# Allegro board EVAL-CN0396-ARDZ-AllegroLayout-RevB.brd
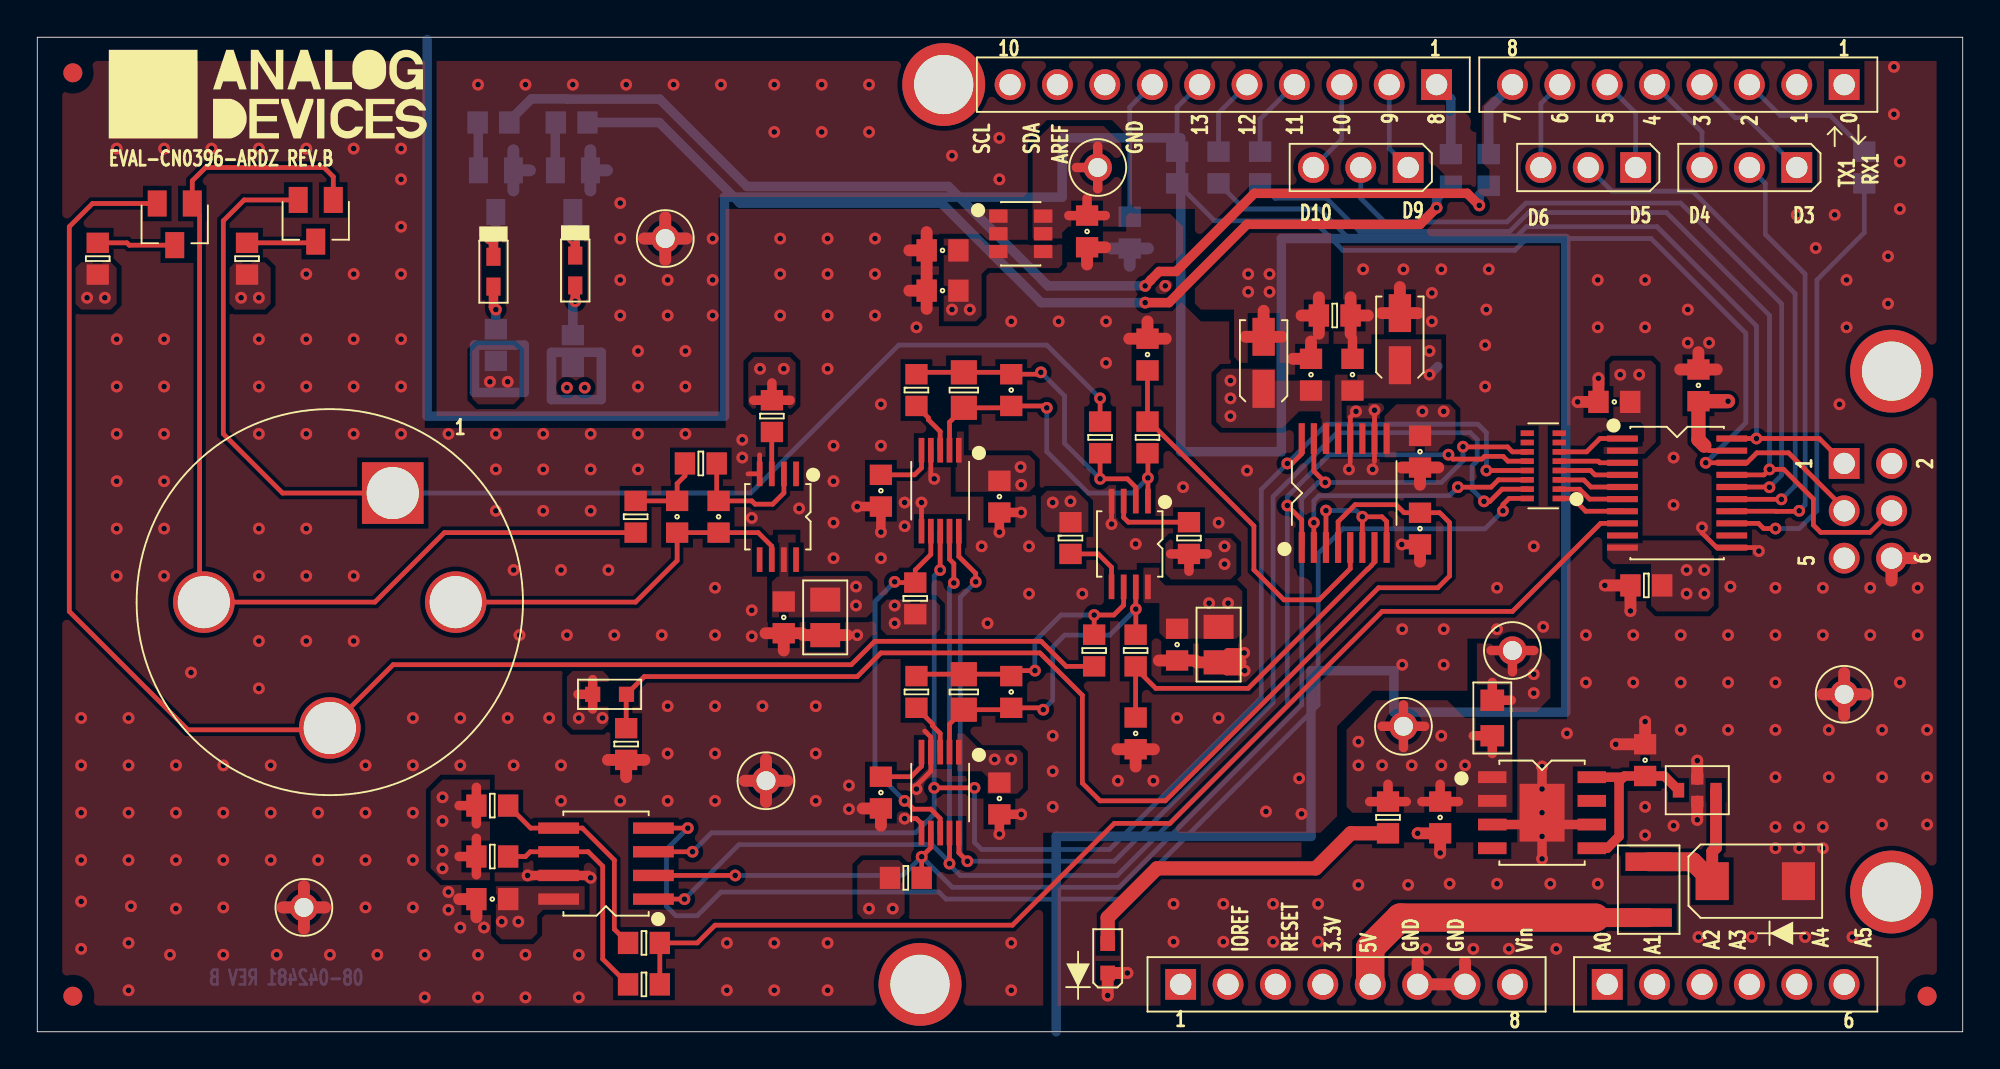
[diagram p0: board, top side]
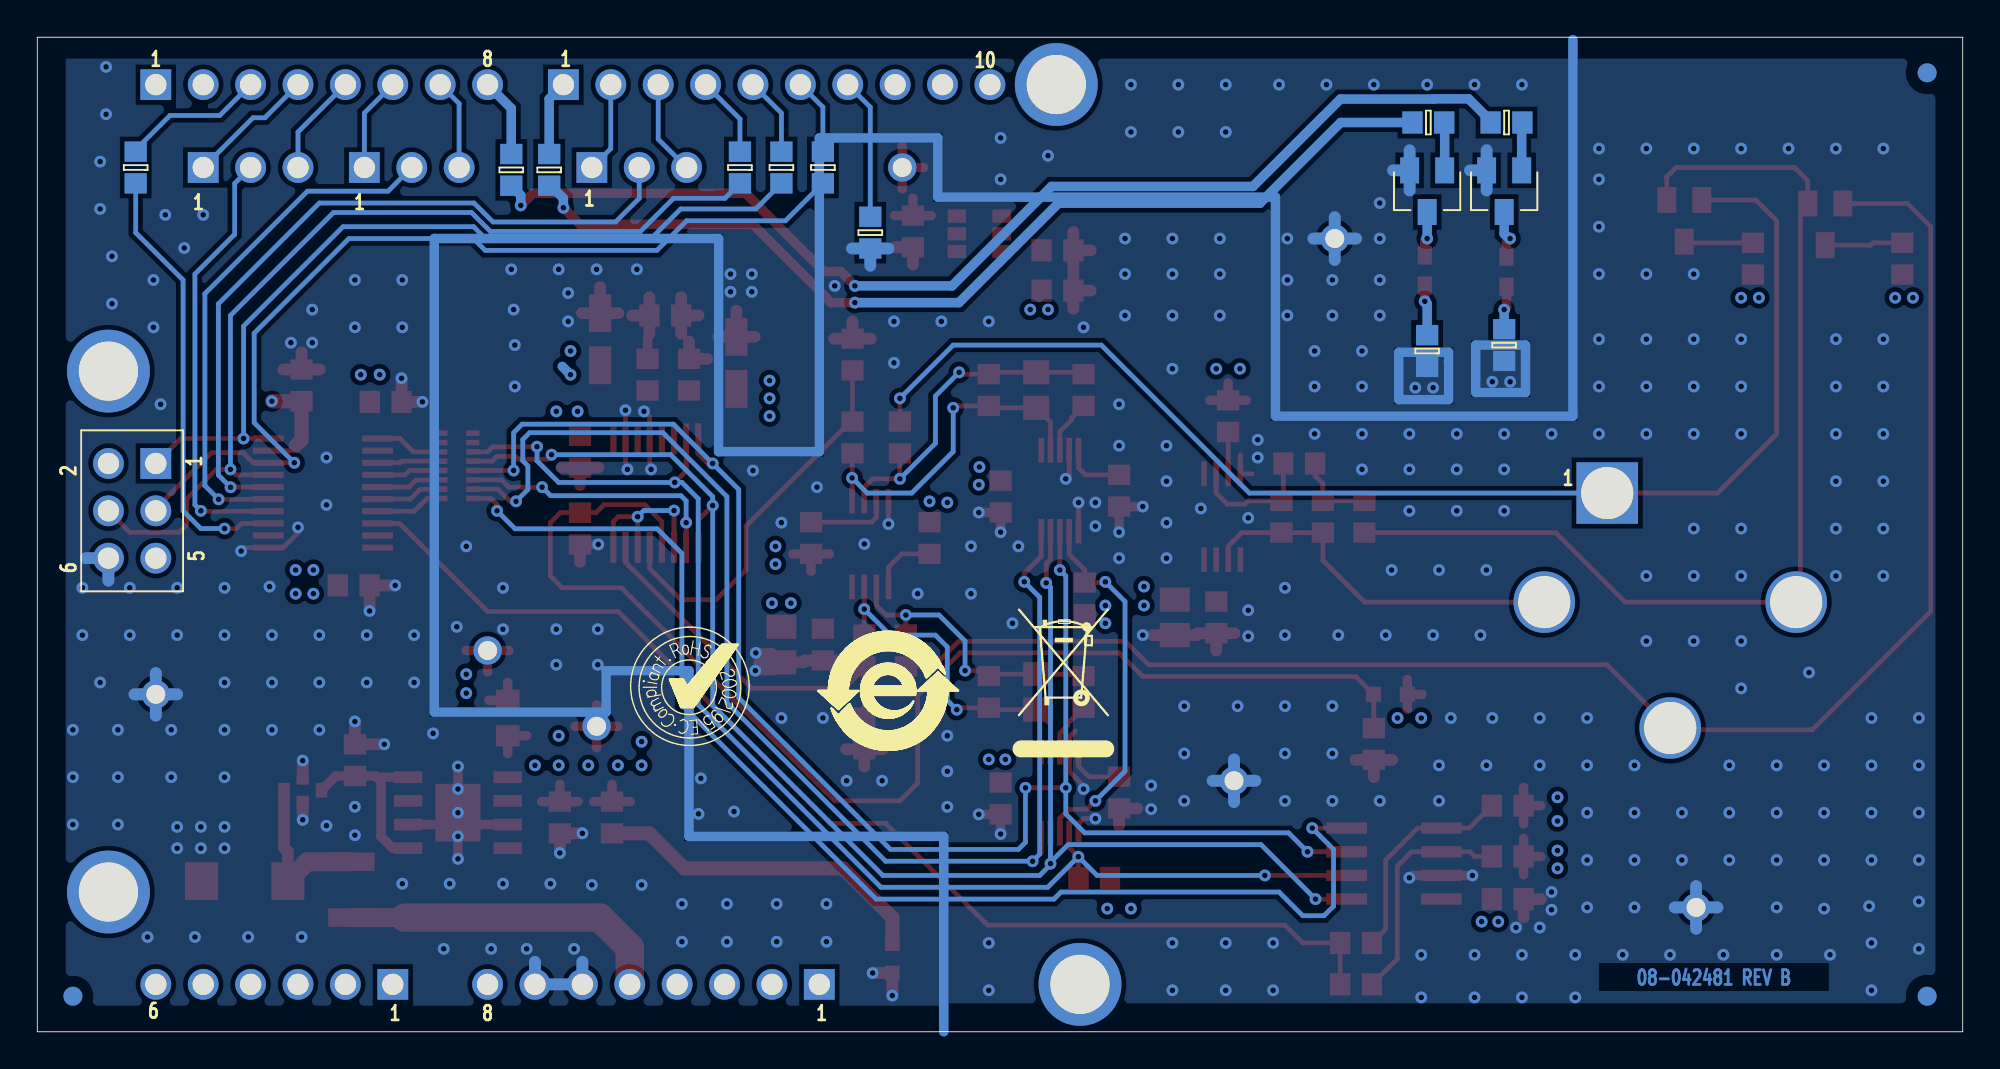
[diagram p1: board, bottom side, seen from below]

Outline 103.19 x 53.34 mm; copper layers: TOP, L2_GND, L3_PWR, BOTTOM. Coordinates in mm from the lower left corner of the outline.
Outline path: 0,53.34 0,0 103.19,0 103.19,53.34 0,53.34

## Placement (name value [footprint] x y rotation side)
A1  ADA4528-2ARMZ  [MSOP8]  58.55 26.16 180 top
A2  ADA4528-1ARMZ  [MSOP8]  39.69 27.62 180 top
AD5270_CS  SAMTECTSW10608GS3PIN  [CNBERG1X3H205LD36]  85.66 46.36 180 top
AD7798_CS  SAMTECTSW10608GS3PIN  [CNBERG1X3H205LD36]  73.47 46.36 180 top
ADT7310_CS  SAMTECTSW10608GS3PIN  [CNBERG1X3H205LD36]  94.3 46.36 180 top
ANALOG  SSQ-106-03-G-S  [CNSAMTECSSQ-106-XX-X-S]  84.14 2.54 0 top
C1  1uF  [C0603]  48.51 39.75 180 top
C2  0.1uF  [C0603]  48.51 41.91 180 top
C3  0.022uF  [C0603]  36.51 27.62 270 top
C4  0.022uF  [C0603]  34.29 27.62 90 top
C5  0.1uF  [C0603]  56.26 42.93 270 top
C6  4.7uF  [C0805H53]  42.23 22.23 270 top
C7  0.1uF  [C0603]  40 22.23 270 top
C8  0.022uF  [C0603]  52.2 34.42 270 top
C9  10uF  [C0603]  59.5 36.32 90 top
C10  0.1uF  [C0603]  51.56 28.7 270 top
C11  1uF  [C0603]  45.21 29.02 270 top
C12  1.0UF  [C0805-4P]  88.96 12.95 180 top
C13  1uF  [C0603]  86.17 14.57 90 top
C14  1uF  [C0603]  75.18 11.49 270 top
C15  0.1uF  [C0603]  51.56 12.51 270 top
C16  1uF  [C0603]  45.21 12.83 270 top
C17  4.7uF  [C0805H53]  63.31 20.76 270 top
C18  0.1uF  [C0603]  74.1 31.12 270 top
C19  0.1uF  [C0603]  61.09 20.76 270 top
C20  0.1uF  [C0603]  70.48 35.24 270 top
C21  0.1uF  [C0603]  89.03 34.67 270 top
C22  0.1uF  [C0603]  84.52 33.78 180 top
C23  0.022uF  [C0603]  52.2 18.22 270 top
C24  10uF  [C0603]  58.86 16 270 top
C25  0.1uF  [C0603]  24.38 7.11 180 top
C26  0.1uF  [C0603]  74.1 26.99 270 top
C27  10uF  [C3216]  73.03 37.15 90 top
C28  10uF  [C3216]  65.72 35.88 90 top
C29  0.1uF  [C0603]  68.26 35.24 90 top
CR1  1SMB5927BT3G  [DO214AA]  92.08 8.08 0 top
DGND1  5001  [CNKEY5001TP]  33.66 42.55 0 top
DGND2  5001  [CNKEY5001TP]  96.84 18.1 0 top
DIGI0  SSQ-108-03-G-S  [CNSAMTECSSQ-108-XX-X-S]  96.84 50.8 180 top
DIGI1  SSQ-110-03-G-S  [CNSAMTECSSQ-110-XX-X-S]  74.99 50.8 180 top
E1  330OHM  [L0805]  77.98 16.83 90 top
F1  0.35A  [F1210]  86.36 7.62 90 top
GND1  5001  [CNKEY5001TP]  14.29 6.67 0 top
GND2  5001  [CNKEY5001TP]  39.05 13.46 0 top
ICSP  SSQ-103-03-G-D  [CNSAMTECSSQ-103-XX-X-D]  96.84 30.48 270 bottom
LED1  LTST-C190CKT  [LED0603]  28.83 40.83 270 top
LED2  LTST-C190CKT  [LED0603]  24.45 40.77 270 top
M1  COH-A2  [MCOH-A2_SKTLD98]  19.05 28.89 180 top
NOREF  -  []  0 0 0 top
NOREF#2  -  []  0 53.34 270 top
NOREF#3  -  [unnamed#2]  101.28 1.91 0 top
NOREF#4  -  []  180.15 63.37 0 top
NOREF#5  -  []  0 0 0 top
NOREF#6  -  []  101.28 1.91 0 top
NOREF#7  -  []  -111.82 -234.12 0 top
NOREF#8  -  [unnamed#2]  47.31 2.54 0 top
NOREF#9  -  [unnamed#2]  1.91 51.44 0 top
NOREF#10  -  []  103.19 53.34 0 top
NOREF#11  -  []  -111.82 -234.12 0 top
NOREF#12  -  [unnamed#2]  99.38 35.43 0 top
NOREF#13  -  []  -36.77 -49.28 0 top
NOREF#14  -  []  0 53.34 0 top
NOREF#15  -  [unnamed#2]  48.58 50.81 0 top
NOREF#16  -  []  12.38 50.29 0 top
NOREF#17  -  []  103.19 0 0 top
NOREF#18  -  []  59.12 76.07 0 top
NOREF#19  -  []  0 0 90 top
NOREF#20  -  []  101.28 1.91 0 top
NOREF#21  -  []  -11.94 12.65 0 top
NOREF#22  -  []  103.19 0 0 top
NOREF#23  -  [unnamed#2]  1.91 1.91 0 top
NOREF#24  -  []  103.19 53.34 180 top
NOREF#25  -  []  103.19 0 90 top
NOREF#26  -  [unnamed#2]  99.38 7.49 0 top
NOREF#27  -  []  -63.94 154.56 0 top
NOREF#28  -  []  -111.82 -234.12 0 top
NOREF#29  -  []  20.59 22.13 0 top
NOREF#30  -  [unnamed#2]  101.28 1.91 180 bottom
NOREF#31  -  [unnamed#2]  1.91 51.44 180 bottom
NOREF#32  -  []  68.26 18.42 180 bottom
NOREF#33  -  []  57.59 18.29 180 bottom
NOREF#34  -  []  48.2 19.81 180 bottom
NOREF#35  -  [unnamed#2]  1.91 1.91 180 bottom
P1  SSQ-108-03-G-S  [CNSAMTECSSQ-108-XX-X-S]  61.28 2.54 0 top
POWER  SML-LX0603GW-TR  [LED0603-2]  57.37 3.94 90 top
Q1  MMBFJ270  [SOT23]  14.92 43.5 180 top
Q2  MMBFJ270  [SOT23]  7.37 43.31 180 top
Q3  MMBT2222A  [SOT23]  28.7 45.09 0 bottom
Q4  MMBT2222A  [SOT23]  24.57 45.09 0 bottom
R1  12.4K  [R0603]  39.37 33.02 270 top
R2  12.4K  [R0603]  35.56 30.48 180 top
R3  12.4K  [R0603]  32.07 27.62 270 top
R4  1MEG  [R0603]  11.24 41.47 90 top
R5  33  [R0603]  56.96 31.88 270 top
R6  165  [R0603]  72.39 11.49 270 top
R7  12.4K  [R0603]  61.72 26.48 90 top
R8  TBD0805  [R0805]  49.66 34.42 270 top
R9  100K  [R0603]  59.5 31.88 90 top
R10  33  [R0603]  56.64 20.45 90 top
R11  12.4K  [R0603]  55.37 26.48 270 top
R12  TBD0805  [R0805]  49.66 18.22 270 top
R13  100K  [R0603]  58.86 20.45 270 top
R14  0  [R0603]  65.53 46.36 90 bottom
R15  0  [R0603]  63.31 46.36 90 bottom
R16  0  [R0603]  61.09 46.36 90 bottom
R17  0  [R0603]  58.55 42.86 90 bottom
R18  100K  [R0603]  86.23 23.94 180 top
R19  2.2K  [R0603]  47.05 23.24 270 top
R20  100K  [R0603]  24.38 12.13 0 top
R21  100K  [R0603]  24.38 9.4 0 top
R22  2.2K  [R0603]  46.55 8.25 180 top
R23  1MEG  [R0603]  3.24 41.47 90 top
R24  0  [R0603]  47.12 34.42 270 top
R25  0  [R0603]  47.12 18.22 270 top
R26  18.7K  [R0603]  31.56 15.43 270 top
R27  1K  [R0603]  28.64 48.77 180 bottom
R28  249  [R0603]  28.7 36.51 90 bottom
R29  1K  [R0603]  24.45 48.77 180 bottom
R30  249  [R0603]  24.57 36.83 90 bottom
R31  0  [R0603]  69.53 38.42 180 top
R32  0  [R0603]  97.92 46.36 90 bottom
R33  0  [R0603]  32.51 4.76 180 top
R34  0  [R0603]  32.51 2.54 180 top
R35  0  [R0603]  75.76 46.23 90 bottom
R36  0  [R0603]  77.79 46.23 90 bottom
REF  5002  [CNKEY5001TP]  56.83 46.36 90 top
RN1  47  [RESNET16]  80.71 30.35 90 top
RT1  10K  [R0603H35]  30.67 18.1 180 top
U1  AD7798BRUZ  [TSSOP16]  70.04 28.89 0 top
U2  AD5270BRMZ-20  [RM10]  48.39 29.02 180 top
U3  AD5270BRMZ-20  [RM10]  48.39 12.83 180 top
U4  ADT7310TRZ  [SO8]  30.48 9.02 90 top
U5  ADR3412ARJZ  [SOT23_6-2]  52.7 42.8 270 top
U6  ADP7102ARDZ-3.3  [SO8NB-PAD3_1X2_41]  80.64 11.75 270 top
U7  TXB0108PWR  [TSSOP20]  87.88 28.89 270 top
UNK3V3A  5002  [CNKEY5001TP]  73.22 16.38 0 top
UNK3V3D  5002  [CNKEY5001TP]  79.06 20.45 0 top

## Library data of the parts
A1 = ADA4528_2: Tolerance: N/A; User Part Number: UPN; part number: ADA4528_2_SM-ADA4528-2ARMZ,E018592,MSOP8; tolerance: N/A
A2 = ADOPAMP1V4: Tolerance: N/A; User Part Number: UPN; part number: ADOPAMP1V4_SM-ADA4528-1ARMZ,E014981,MSOP8; tolerance: N/A
AD5270_CS AD7798_CS ADT7310_CS = CN3P: User Part Number: UPN; Tolerance: N/A; part number: CN3P_TH-SAMTECTSW10608GS3PIN,E000812,CNBERG1X3H205LD36; tolerance: N/A
ANALOG = CN6P: User Part Number: UPN; Tolerance: N/A; part number: CN6P_TH-SSQ-106-03-G-S,E020477,CNSAMTECSSQ-106-XX-X-S; tolerance: N/A
C1 C11 C13 C14 C16 = CAP: Tolerance: 10; User Part Number: UPN; part number: CAP_SM-1UF,16V,10,E006882,C0603; tolerance: 10
C2 C5 C7 C10 C15 C18-C22 C25 C26 C29 = CAP: Tolerance: 10; User Part Number: UPN; part number: CAP_SM-0.1UF,25V,10,E022366,C0603; tolerance: 10
C3 C4 C8 C23 = CAP: Tolerance: 10; User Part Number: UPN; part number: CAP_SM-0.022UF,50V,10,E015725,C0603; tolerance: 10
C6 C17 = CAP: Tolerance: 10; User Part Number: UPN; part number: CAP_SM-4.7UF,25V,10,E006908,C0805H53; tolerance: 10
C9 C24 = CAP: Tolerance: 20; User Part Number: UPN; part number: CAP_SM-10UF,10V,20,E022682,C0603; tolerance: 20
C12 = CAP4P_V3: Tolerance: 20; User Part Number: UPN; part number: CAP4P_V3_SM-1.0UF,16V,20,E014204,C0805-4P; tolerance: 20
C27 C28 = CAPP: Tolerance: 10; User Part Number: UPN; part number: CAPP_SM-10UF,10V,10,E000690,C3216; tolerance: 10
CR1 = DIOZNR: User Part Number: UPN; Tolerance: N/A; part number: DIOZNR_SM-1SMB5927BT3G,12V,N/A,E006923,DO214AA; tolerance: N/A
DGND1 DGND2 GND1 GND2 = CNTP1P: Tolerance: N/A; User Part Number: UPN; part number: CNTP1P_TH-5001,E005347,CNKEY5001TP; tolerance: N/A
DIGI0 P1 = CN8P_A: User Part Number: UPN; Tolerance: N/A; part number: CN8P_A_TH-SSQ-108-03-G-S,E020478,CNSAMTECSSQ-108-XX-X-S; tolerance: N/A
DIGI1 = CN10P: User Part Number: UPN; Tolerance: N/A; part number: CN10P_TH-SSQ-110-03-G-S,E020479,CNSAMTECSSQ-110-XX-X-S; tolerance: N/A
E1 = FERRITE: Tolerance: 25; User Part Number: UPN; part number: FERRITE_SM-330OHM,25,E018120,L0805; tolerance: 25
F1 = FSFUSE: Tolerance: N/A; User Part Number: UPN; part number: FSFUSE_SM-0.35A,6V,E016918,F1210; tolerance: N/A
ICSP = CN6P: User Part Number: UPN; Tolerance: N/A; part number: CN6P_TH-SSQ-103-03-G-D,E020488,CNSAMTECSSQ-103-XX-X-D; tolerance: N/A
LED1 LED2 = DIOLED: Tolerance: N/A; User Part Number: UPN; part number: DIOLED_SM-LTST-C190CKT,1.8V,N/A,E023763,LED0603; tolerance: N/A
M1 = MOD_COH_A2: User Part Number: UPN; Tolerance: N/A; part number: MOD_COH_A2_TH-COH-A2,E024920,MCOH-A2_SKTLD98; tolerance: N/A
POWER = DIOLED: Tolerance: N/A; User Part Number: UPN; part number: DIOLED_SM-SML-LX0603GW-TR,2.2V,N/A,E018702,LED0603-2; tolerance: N/A
Q1 Q2 = TRANPJFET: User Part Number: UPN; Tolerance: N/A; part number: TRANPJFET_SM-MMBFJ270,E020756,SOT23; tolerance: N/A
Q3 Q4 = TRANMMBT4401: User Part Number: UPN; Tolerance: N/A; part number: TRANMMBT4401_SM-MMBT2222A,E006594,SOT23; tolerance: N/A
R1-R3 R7 R11 = RES: Tolerance: 1; User Part Number: UPN; part number: RES_SM-12.4K,E015341,1/10W,1,R0603; tolerance: 1
R4 R23 = RES: Tolerance: 1; User Part Number: UPN; part number: RES_SM-1MEG,E003682,1/10W,1,R0603; tolerance: 1
R5 R10 = RES: Tolerance: 5; User Part Number: UPN; part number: RES_SM-33,E026149,1/10W,5,R0603; tolerance: 5
R6 = RES: Tolerance: 1; User Part Number: UPN; part number: RES_SM-165,E003725,1/10W,1,R0603; tolerance: 1
R8 R12 = RES: User Part Number: UPN; part number: RES_SM-TBD0805,E004051,TBD0805,TBD0805,R0805
R9 R13 R18 R20 R21 = RES: Tolerance: 1; User Part Number: UPN; part number: RES_SM-100K,E010279,1/10W,1,R0603; tolerance: 1
R14-R17 R24 R25 R31-R36 = RES: Tolerance: 5; User Part Number: UPN; part number: RES_SM-0,E006826,1/10W,5,R0603; tolerance: 5
R19 R22 = RES: Tolerance: 1; User Part Number: UPN; part number: RES_SM-2.2K,E014667,1/10W,1,R0603; tolerance: 1
R26 = RES: Tolerance: 1; User Part Number: UPN; part number: RES_SM-18.7K,E011248,1/10W,1,R0603; tolerance: 1
R27 R29 = RES: Tolerance: 1; User Part Number: UPN; part number: RES_SM-1K,E003678,1/10W,1,R0603; tolerance: 1
R28 R30 = RES: Tolerance: 1; User Part Number: UPN; part number: RES_SM-249,E003684,1/10W,1,R0603; tolerance: 1
REF UNK3V3A UNK3V3D = CNTP1P: Tolerance: N/A; User Part Number: UPN; part number: CNTP1P_TH-5002,E006153,CNKEY5001TP; tolerance: N/A
RN1 = RESNET_16P_8R: Tolerance: 5; User Part Number: UPN; part number: RESNET_16P_8R_SM-47,E004467,1/16W,5,RESNET16; tolerance: 5
RT1 = RESTHERM: Tolerance: 1; User Part Number: UPN; part number: RESTHERM_SM-10K,E025118,0.1W,1,R0603H35; tolerance: 1
U1 = AD779X: Tolerance: N/A; User Part Number: UPN; part number: AD779X_SM-AD7798BRUZ,E014198,TSSOP16; tolerance: N/A
U2 U3 = AD5X7X: Tolerance: N/A; User Part Number: UPN; part number: AD5X7X_SM-AD5270BRMZ-20,E018108,RM10; tolerance: N/A
U4 = ADT7310: Tolerance: N/A; User Part Number: UPN; part number: ADT7310_SM-ADT7310TRZ,E017246,SO8; tolerance: N/A
U5 = ADR34XX: User Part Number: UPN; Tolerance: N/A; part number: ADR34XX_SM-ADR3412ARJZ,E015880,SOT23_6-2; tolerance: N/A
U6 = ADP7102: Tolerance: N/A; User Part Number: UPN; part number: ADP7102_SM-ADP7102ARDZ-3.3,E016891,SO8NB-PAD3_1X2_41; tolerance: N/A
U7 = ICTXB0108: Tolerance: N/A; User Part Number: UPN; part number: ICTXB0108_SM-TXB0108PWR,E019338,TSSOP20; tolerance: N/A

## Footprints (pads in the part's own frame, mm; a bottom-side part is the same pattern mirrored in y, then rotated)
C0603
  rect 1.092x1.194 smd: 1(-0.851,0) 2(0.851,0)
C0805-4P
  rect 0.61x0.787 smd: 1(-1.005,0) 3(1.005,0)
  rect 0.66x0.61 smd: G1(0,-0.605) G2(0,0.605)
C0805H53
  rect 1.295x1.6 smd: 1(-0.953,0) 2(0.953,0)
C3216
  rect 2.032x1.194 smd: N(1.397,0) P(-1.397,0)
CNBERG1X3H205LD36
  rect 1.651x1.651 hole 1.143: 1(0,0)
  round 1.651 hole 1.143: 2(2.54,0) 3(5.08,0)
CNKEY5001TP
  round 1.524 hole 1.016: 1(0,0)
CNSAMTECSSQ-103-XX-X-D
  rect 1.651x1.651 hole 1.143: 1(0,0)
  round 1.651 hole 1.143: 2(0,-2.54) 3(2.54,0) 4(2.54,-2.54) 5(5.08,0) 6(5.08,-2.54)
CNSAMTECSSQ-106-XX-X-S
  rect 1.651x1.651 hole 1.143: 1(0,0)
  round 1.651 hole 1.143: 2(2.54,0) 3(5.08,0) 4(7.62,0) 5(10.16,0) 6(12.7,0)
CNSAMTECSSQ-108-XX-X-S
  rect 1.651x1.651 hole 1.143: 1(0,0)
  round 1.651 hole 1.143: 2(2.54,0) 3(5.08,0) 4(7.62,0) 5(10.16,0) 6(12.7,0) 7(15.24,0) 8(17.78,0)
CNSAMTECSSQ-110-XX-X-S
  rect 1.651x1.651 hole 1.143: 1(0,0)
  round 1.651 hole 1.143: 2(2.54,0) 3(5.08,0) 4(7.62,0) 5(10.16,0) 6(12.7,0) 7(15.24,0) 8(17.78,0) 9(20.32,0) 10(22.86,0)
DO214AA
  rect 1.778x2.032 smd: A(2.311,0) C(-2.311,0)
F1210
  rect 0.991x2.489 smd: 1(-1.499,0) 2(1.499,0)
L0805
  rect 1.143x1.27 smd: 1(-0.953,0) 2(0.953,0)
LED0603
  rect 0.965x0.762 smd: A(0.8,0) C(-0.8,0)
LED0603-2
  rect 0.787x0.787 smd: A(0.787,0) C(-0.787,0)
MCOH-A2_SKTLD98
  rect 3.302x3.302 hole 2.794: 1(0,0)
  round 3.302 hole 2.794: 2(-3.375,5.85) 3(3.375,12.6) 4(10.125,5.85)
MSOP8
  rect 0.305x1.321 smd: 1(-0.975,-2.3) 2(-0.325,-2.3) 3(0.325,-2.3) 4(0.975,-2.3) 5(0.975,2.3) 6(0.325,2.3) 7(-0.325,2.3) 8(-0.975,2.3)
R0603
  rect 1.092x1.194 smd: 1(-0.851,0) 2(0.851,0)
R0603H35
  rect 0.813x0.813 smd: 1(-0.907,0) 2(0.907,0)
R0805
  rect 1.295x1.397 smd: 1(-0.953,0) 2(0.953,0)
RESNET16
  rect 0.305x0.711 smd: 1(-1.75,-0.856) 2(-1.25,-0.856) 3(-0.75,-0.856) 4(-0.25,-0.856) 5(0.25,-0.856) 6(0.75,-0.856) 7(1.25,-0.856) 8(1.75,-0.856) 9(1.75,0.856) 10(1.25,0.856) 11(0.75,0.856) 12(0.25,0.856) 13(-0.25,0.856) 14(-0.75,0.856) 15(-1.25,0.856) 16(-1.75,0.856)
RM10
  rect 0.305x1.321 smd: 1(-1,-2.171) 2(-0.5,-2.171) 3(0,-2.171) 4(0.5,-2.171) 5(1,-2.171) 6(1,2.171) 7(0.5,2.171) 8(0,2.171) 9(-0.5,2.171) 10(-1,2.171)
SO8
  rect 0.61x2.184 smd: 1(-1.905,-2.54) 2(-0.635,-2.54) 3(0.635,-2.54) 4(1.905,-2.54) 5(1.905,2.54) 6(0.635,2.54) 7(-0.635,2.54) 8(-1.905,2.54)
SO8NB-PAD3_1X2_41
  rect 0.635x1.524 smd: 1(-1.905,-2.667) 2(-0.635,-2.667) 3(0.635,-2.667) 4(1.905,-2.667) 5(1.905,2.667) 6(0.635,2.667) 7(-0.635,2.667) 8(-1.905,2.667)
  rect 3.099x2.413 smd: PAD(0,0)
SOT23
  rect 1.016x1.397 smd: 1(-0.94,-1.118) 2(0.94,-1.118) 3(0,1.118)
SOT23_6-2
  rect 0.711x0.991 smd: 1(-0.95,-1.2) 2(0,-1.2) 3(0.95,-1.2) 4(0.95,1.2) 5(0,1.2) 6(-0.95,1.2)
TSSOP16
  rect 0.33x1.651 smd: 1(-2.275,-2.92) 2(-1.625,-2.92) 3(-0.975,-2.92) 4(-0.325,-2.92) 5(0.325,-2.92) 6(0.975,-2.92) 7(1.625,-2.92) 8(2.275,-2.92) 9(2.275,2.92) 10(1.625,2.92) 11(0.975,2.92) 12(0.325,2.92) 13(-0.325,2.92) 14(-0.975,2.92) 15(-1.625,2.92) 16(-2.275,2.92)
TSSOP20
  rect 0.33x1.651 smd: 1(-2.925,-2.93) 2(-2.275,-2.93) 3(-1.625,-2.93) 4(-0.975,-2.93) 5(-0.325,-2.93) 6(0.325,-2.93) 7(0.975,-2.93) 8(1.625,-2.93) 9(2.275,-2.93) 10(2.925,-2.93) 11(2.925,2.93) 12(2.275,2.93) 13(1.625,2.93) 14(0.975,2.93) 15(0.325,2.93) 16(-0.325,2.93) 17(-0.975,2.93) 18(-1.625,2.93) 19(-2.275,2.93) 20(-2.925,2.93)
unnamed#2
  round 1.016 smd: (0,0)

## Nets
1V2_REF: C5.1(N1) C18.1(N1) R1.1(N1) R7.1(N1) R11.1(N1) REF.1(N1) RT1.2(N2) U1.3(AIN3_POS_P1) U1.6(AIN1_NEG) U1.8(AIN2_NEG) U1.9(REFIN_POS) U5.5(VOUT_SENSE) U5.6(VOUT_FORCE)
3V3A: A1.8(V+) A2.7(V+) C1.1(N1) C2.1(N1) C6.1(N1) C7.1(N1) C10.1(N1) C15.1(N1) C17.1(N1) C19.1(N1) C20.2(N2) C25.1(N1) C27.P(N1) E1.2(N2) R4.1(N1) R19.2(N2) R20.1(N1) R21.1(N1) R22.2(N2) R23.1(N1) U1.13(AVDD) U2.1(VDD) U3.1(VDD) U4.8(VDD) U5.3(ENABLE) U5.4(VIN) UNK3V3D.1
3V3D: C14.1(N1) C22.1(N1) C28.P(N1) C29.1(N1) E1.1(N1) R6.1(N1) R18.1(N1) R28.1(N1) R30.1(N1) U1.14(DVDD) U6.1(VOUT) U6.2(SENSE_ADJ) U7.2(VCCA) U7.10(OE) UNK3V3A.1
5V_ARD: F1.1(N1) P1.5(N5)
AGND: A1.4(V-) A2.4(V-) C1.2(N2) C2.2(N2) C5.2(N2) C6.2(N2) C7.2(N2) C9.2(N2) C10.2(N2) C11.2(N2) C15.2(N2) C16.2(N2) C17.2(N2) C18.2(N2) C19.2(N2) C20.1(N1) C24.2(N2) C25.2(N2) C26.2(N2) C27.N(N2) GND1.1(N1) GND2.1(N1) R17.1(N1) R26.2(N2) R31.1(N1) U1.10(REFIN_NEG) U1.12(GND) U2.4(VSS) U2.6(GND) U3.4(VSS) U3.6(GND) U4.7(GND) U5.1(GND_FORCE) U5.2(GND_SENSE)
DGND: C12.G1(GND1) C12.G2(GND2) C13.2(N2) C14.2(N2) C21.1(N1) C22.2(N2) C28.N(N2) C29.2(N2) CR1.A(P) DGND1.1(N1) DGND2.1(N1) ICSP.6(N6) P1.6(N6) P1.7(N7) POWER.C(N) Q3.2(E) Q4.2(E) R18.2(N2) R31.2(N2) U6.3(GND1) U6.6(GND2) U6.PAD U7.11(GND)
CS: RN1.14(N2) U1.2(CS_N)
CS1: AD7798_CS.2(N2) U7.16(B4)
CS2: AD5270_CS.2(N2) U7.15(B5)
CS3: ADT7310_CS.2(N2) U7.14(B6)
CS_POT: RN1.15(N2) U2.10(SYNC_N) U3.10(SYNC_N)
CS_TEMP: RN1.16(N2) U4.4(CS*)
CT_TEMP: R21.2(N2) R34.2(N2) U4.6(CT)
DC: R19.1(N1) U2.7(SDO) U3.8(DIN)
INT: R32.1(N1) U7.13(B7)
INT_TEMP: R20.2(N2) R33.2(N2) U4.5(INT)
IOREF: C21.2(N2) P1.2(N2) U7.19(VCCB)
LED1: R27.1(N1) R35.1(N1)
LED2: R29.1(N1) R36.1(N1)
MISO: R22.1(N1) RN1.11(N2) U1.15(DOUT_RDY_N) U3.7(SDO) U4.2(DOUT)
MISO_ARD: ICSP.1(N1) R15.1(N1) U7.20(B1)
MOSI: RN1.13(N2) U1.16(DIN) U2.8(DIN) U4.3(DIN)
MOSI_ARD: ICSP.4(N4) R14.1(N1) U7.17(B3)
SCLK: RN1.12(N2) U1.1(SCLK) U2.9(SCLK) U3.9(SCLK) U4.1(SCLK)
SCLK_ARD: ICSP.3(N3) R16.1(N1) U7.18(B2)
UNNAMED_6_AD5X7X_I72_A: A1.7(OUT) C23.2(N2) R12.2(N2) R13.1(N1) U3.2(A)
UNNAMED_6_AD5X7X_I72_EXTCAP: C16.1(N1) U3.5(EXT_CAP)
UNNAMED_6_AD5X7X_I72_W: R25.2(N2) U3.3(W)
UNNAMED_6_AD5X7X_I117_A: A1.1(OUT) C8.2(N2) R8.2(N2) R9.1(N1) U2.2(A)
UNNAMED_6_AD5X7X_I117_EXTCAP: C11.1(N1) U2.5(EXT_CAP)
UNNAMED_6_AD5X7X_I117_W: R24.2(N2) U2.3(W)
UNNAMED_6_AD779X_I99_AIN3NEGP2: C26.1(N1) R26.1(N1) RT1.1(N1) U1.4(AIN3_NEG_P2)
UNNAMED_6_ADA45282_I56_: A1.5(+IN) R11.2(N2)
UNNAMED_6_ADA45282_I56__1: A1.6(-IN) C23.1(N1) R10.2(N2) R12.1(N1) R25.1(N1)
UNNAMED_6_ADA45282_I112_: A1.2(-IN) C8.1(N1) R5.2(N2) R8.1(N1) R24.1(N1)
UNNAMED_6_ADA45282_I112__1: A1.3(+IN) R7.2(N2)
UNNAMED_6_ADOPAMP1V4_I123_INV: A2.2(INV) C3.1(N1) R2.1(N1)
UNNAMED_6_ADOPAMP1V4_I123_NINV: A2.3(NINV) R1.2(N2)
UNNAMED_6_ADOPAMP1V4_I123_OUT: A2.6(OUT) C3.2(N2) C4.1(N1) M1.2(CE)
UNNAMED_6_CAP_I58_N2: C4.2(N2) R2.2(N2) R3.1(N1)
UNNAMED_6_CAP_I76_N1: C24.1(N1) R13.2(N2) U1.7(AIN2_POS)
UNNAMED_6_CAP_I106_N1: C9.1(N1) R9.2(N2) U1.5(AIN1_POS)
UNNAMED_6_DIOLED_I150_N: LED1.C(N) Q3.3(C)
UNNAMED_6_DIOLED_I150_P: LED1.A(P) R28.2(N2)
UNNAMED_6_DIOLED_I151_N: LED2.C(N) Q4.3(C)
UNNAMED_6_DIOLED_I151_P: LED2.A(P) R30.2(N2)
UNNAMED_6_MODCOHA2_I100_RE: M1.4(RE) Q1.1(D) Q2.1(D) R3.2(N2)
UNNAMED_6_RES_I73_N2: Q1.3(G) R4.2(N2)
UNNAMED_6_RES_I121_N2: Q2.3(G) R23.2(N2)
UNNAMED_6_RES_I138_N2: Q3.1(B) R27.2(N2)
UNNAMED_6_RES_I142_N2: Q4.1(B) R29.2(N2)
UNNAMED_7_ADP7102_I29_ENUVLO: C12.3(OUT) C13.1(N1) U6.5(EN_UVLO) U6.8(VIN)
UNNAMED_7_CAP4PV3_I7_IN: C12.1(IN) CR1.C(N) F1.2(N2)
UNNAMED_7_DIOLED_I21_P: POWER.A(P) R6.2(N2)
UNNAMED_8_CN3P_I101_N1: AD5270_CS.1(N1) DIGI0.6(N6)
UNNAMED_8_CN3P_I101_N3: AD5270_CS.3(N3) DIGI0.7(N7)
UNNAMED_8_CN3P_I102_N1: ADT7310_CS.1(N1) DIGI0.4(N4)
UNNAMED_8_CN3P_I102_N3: ADT7310_CS.3(N3) DIGI0.5(N5)
UNNAMED_8_CN8PA_I81_N3: DIGI0.3(N3) R32.2(N2)
UNNAMED_8_CN8PA_I81_N8: DIGI0.8(N8) R36.2(N2)
UNNAMED_8_CN10P_I85_N1: DIGI1.1(N1) R35.2(N2)
UNNAMED_8_CN10P_I85_N2: AD7798_CS.1(N1) DIGI1.2(N2)
UNNAMED_8_CN10P_I85_N3: AD7798_CS.3(N3) DIGI1.3(N3)
UNNAMED_8_CN10P_I85_N4: DIGI1.4(N4) R14.2(N2)
UNNAMED_8_CN10P_I85_N5: DIGI1.5(N5) R15.2(N2)
UNNAMED_8_CN10P_I85_N6: DIGI1.6(N6) R16.2(N2)
UNNAMED_8_CN10P_I85_N7: DIGI1.7(N7) R17.2(N2)
UNNAMED_8_ICTXB0108_I64_A1: RN1.6(N1) U7.1(A1)
UNNAMED_8_ICTXB0108_I64_A2: RN1.5(N1) U7.3(A2)
UNNAMED_8_ICTXB0108_I64_A3: RN1.4(N1) U7.4(A3)
UNNAMED_8_ICTXB0108_I64_A4: RN1.3(N1) U7.5(A4)
UNNAMED_8_ICTXB0108_I64_A5: RN1.2(N1) U7.6(A5)
UNNAMED_8_ICTXB0108_I64_A6: RN1.1(N1) U7.7(A6)
UNNAMED_8_ICTXB0108_I64_A7: R33.1(N1) R34.1(N1) U7.8(A7)
WORKER1: M1.1(CO_E) Q1.2(S) R5.1(N1)
WORKER2: M1.3(H2S_E) Q2.2(S) R10.1(N1)

Pads without a net: A2 1 5 8; ANALOG 1 2 3 4 5 6; DIGI0 1 2; DIGI1 8 9 10; ICSP 2 5; P1 1 3 4 8; RN1 7 8 9 10; U1 11; U6 4 7; U7 9 12

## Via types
v1: diameter 0.635, hole 0.305, TOP to BOTTOM, 480 vias

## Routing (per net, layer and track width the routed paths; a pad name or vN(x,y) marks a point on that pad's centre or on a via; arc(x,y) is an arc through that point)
1V2_REF: length 27.5
  TOP w0.254: U1.6 v1(71.02,27.62) 72.06,27.62 72.32,27.37 U1.8 ; U1.3 v1(69.07,27.95)
  TOP w0.508: 55.28,43.78 C5.1 ; C5.1 57.24,43.78 ; C5.1 56.26,44.7 ; 60.74,25.63 R7.1 ; R7.1 62.7,25.63 ; R7.1 61.72,24.7 ; 38.39,33.87 R1.1 ; R1.1 39.37,34.8 ; R1.1 40.35,33.87 ; RT1.2 29.76,18.89 ; RT1.2 29.76,17.31 ; RT1.2 28.98,18.1 ; REF.1 56.83,47.5 ; REF.1 56.83,45.21 ; REF.1 55.69,46.36
  L3_PWR w0.635: REF.1 56.83,47.5 ; REF.1 56.83,45.21 ; REF.1 55.69,46.36 ; REF.1 57.98,46.36
  BOTTOM w0.254: v1(69.07,27.95) 70.69,27.95 v1(71.02,27.62)
  vias: v1(29.02,16.83) v1(30.29,16.83) v1(38.73,35.56) v1(40,35.56) v1(54.42,28.38) v1(55.37,28.45) v1(63.63,26.04) v1(63.63,25.08) v1(74.23,33.27) v1(75.37,33.27)
3V3A: length 15.2
  TOP w0.508: 23.53,8.42 R21.1 ; R21.1 23.53,10.38 ; R21.1 22.61,9.4 ; 77.91,20.45 UNK3V3D.1 ; UNK3V3D.1 80.2,20.45 ; UNK3V3D.1 79.06,19.3 ; R20.1 23.53,13.11 ; R20.1 22.61,12.13 ; R20.1 23.53,11.15 ; 78.99,17.78 E1.2 77.98,18.73
  L3_PWR w0.635: UNK3V3D.1 80.2,20.45 ; UNK3V3D.1 77.91,20.45 ; UNK3V3D.1 79.06,19.3
  BOTTOM w0.508: 75.06,35.69 v1(74.61,35.24)
  vias: v1(2.67,39.37) v1(3.62,39.37) v1(10.92,39.37) v1(11.87,39.37) v1(21.72,12.57) v1(21.72,11.3) v1(21.72,9.72) v1(21.72,8.76) v1(24.89,5.91) v1(25.78,5.91) v1(43.88,23.88) v1(43.88,22.86) v1(44.58,6.6) v1(45.85,6.6) v1(45.95,22.86) v1(45.95,21.91) v1(49.02,38.73) v1(49.97,38.73) v1(51.31,14.6) v1(52.2,14.6) v1(52.7,30.29) v1(52.73,29.34) v1(62.8,22.99) v1(63.82,22.99) v1(74.61,36.51) v1(80.2,19.18) v1(80.2,18.16)
3V3D: length 15.8
  TOP w0.508: 73.22,15.24 UNK3V3A.1 ; UNK3V3A.1 72.07,16.38 ; UNK3V3A.1 74.36,16.38 ; UNK3V3A.1 73.22,17.53 ; 77.98,14.92 E1.1 76.96,15.88 ; R6.1 72.39,13.27 ; R6.1 73.37,12.34 ; R6.1 71.41,12.34 ; C14.1 76.16,12.34 ; C14.1 74.21,12.34 ; C14.1 75.18,13.27
  L3_PWR w0.635: 72.07,16.38 UNK3V3A.1 ; UNK3V3A.1 74.36,16.38 ; UNK3V3A.1 73.22,15.24
  BOTTOM w0.508: 84.9,35.31 v1(84.84,35.24)
  vias: v1(24.26,34.86) v1(25.21,34.86) v1(28.38,34.54) v1(29.34,34.55) v1(63.94,34.93) v1(63.94,33.97) v1(63.94,33.02) v1(70.8,15.56) v1(70.8,14.29) v1(72.07,14.29) v1(73.66,14.29) v1(75.25,15.88) v1(75.25,14.29) v1(76.52,14.29) v1(85.85,35.24) v1(88.39,24.77) v1(88.39,23.5) v1(89.34,24.77) v1(89.34,23.5)
5V_ARD: length 17.6
  TOP w1.016: 83.5,6.12 F1.1
  TOP w1.524: 83.5,6.12 73.05,6.12 71.44,4.51 71.44,2.54
AGND: length 102.6
  TOP w0.254: v1(57.57,27.23) A1.4 ; 38.71,30.95 A2.4 38.09,29.92 ; U2.6 v1(47.39,28.38) ; v1(46.48,11.43) 47.12,11.43 47.39,11.16 U3.6 ; 71.67,30.58 U1.10 v1(71.67,33.34) ; 70.37,30.55 U1.12 70.37,32.96 v1(70.68,33.27) ; 47.56,16.13 47.89,15.8 U3.4 47.89,13.97 47.12,13.2 v1(47.12,13.02) ; v1(48.07,29.65) 47.89,29.84 U2.4
  TOP w0.508: v1(52.73,11.66) C15.2 v1(51.56,10.6) ; v1(26.28,8.38) U4.7 29.53,8.38 v1(29.65,8.25) ; v1(51.56,26.8) C10.2 v1(52.73,27.85) ; v1(64.71,19.37) 63.75,19.37 C17.2 63.82,20.32 v1(64.68,20.32) ; v1(73.13,26.14) C26.2 ; C20.1 70.48,37.21 ; v1(43.94,28.17) C11.2 v1(45.21,26.8)
  TOP w0.635: 31.56,13.65 R26.2 ; R26.2 32.54,14.58 ; R26.2 30.58,14.58 ; 62.13,19.81 C17.2 64.49,19.81 ; 47.66,38.77 C1.2 ; C1.2 47.66,40.73 ; C1.2 46.74,39.75 ; GND1.1 14.29,7.81 ; GND1.1 15.43,6.67 ; GND1.1 13.14,6.67 ; GND1.1 14.29,5.52 ; 47.66,40.93 C2.2 ; C2.2 46.74,41.91 ; C2.2 47.66,42.89 ; 45.21,11.05 C16.2 44.23,11.98 ; GND2.1 40.2,13.46 ; GND2.1 37.91,13.46 ; GND2.1 39.05,14.61 ; GND2.1 39.05,12.32 ; C24.2 59.84,15.15 ; C24.2 58.86,14.22 ; C24.2 57.89,15.15 ; 74.1,25.21 C26.2 ; C9.2 59.5,38.1 ; C9.2 60.48,37.17 ; C9.2 58.52,37.17 ; R31.1 71.31,38.42 ; R31.1 70.38,39.4 ; R31.1 70.38,37.44 ; 40,20.45 C7.2 ; C7.2 40.98,21.37 ; C7.2 39.03,21.37 ; 56.26,41.15 C5.2 57.24,42.08 ; 22.61,7.11 C25.2 23.53,6.13 ; 41.05,21.27 C6.2 43.41,21.27 ; C18.2 75.08,30.26 ; C18.2 73.13,30.26 ; C18.2 74.1,29.34 ; 60.11,19.91 C19.2 62.07,19.91 ; C27.N 73.03,39.94 ; C27.N 74,38.54 ; C27.N 72.05,38.54
  L2_GND w0.635: GND2.1 40.2,13.46 ; GND2.1 37.91,13.46 ; GND2.1 39.05,12.32 ; GND2.1 39.05,14.61 ; 13.14,6.67 GND1.1 ; GND1.1 14.29,5.52 ; GND1.1 14.29,7.81 ; GND1.1 15.43,6.67
  BOTTOM w0.635: GND2.1 40.2,13.46 ; GND2.1 37.91,13.46 ; GND2.1 39.05,14.61 ; GND2.1 39.05,12.32 ; 13.14,6.67 GND1.1 ; GND1.1 14.29,5.52 ; GND1.1 14.29,7.81 ; GND1.1 15.43,6.67 ; 58.55,41.08 R17.1 ; R17.1 57.57,42.01 ; R17.1 59.53,42.01
  vias: v1(2.35,16.83) v1(2.35,14.29) v1(2.35,11.75) v1(2.35,9.21) v1(2.35,6.99) v1(2.35,4.45) v1(4.25,47.37) v1(4.25,37.15) v1(4.25,34.61) v1(4.25,32.07) v1(4.25,29.53) v1(4.25,26.99) v1(4.25,24.45) v1(4.89,16.83) v1(4.89,14.29) v1(4.89,11.75) v1(4.89,9.21) v1(4.89,4.76) v1(4.89,2.22) v1(5.02,6.73) v1(6.79,47.37) v1(6.79,37.15) v1(6.79,34.61) v1(6.79,32.07) v1(6.79,29.53) v1(6.79,26.99) v1(6.79,24.45) v1(7.11,4.13) v1(7.43,14.29) v1(7.43,11.75) v1(7.43,9.21) v1(7.43,6.6) v1(8.24,19.27) v1(9.33,47.37) v1(9.97,14.29) v1(9.97,11.75) v1(9.97,9.21) v1(9.97,6.67) v1(9.97,4.13) v1(11.87,47.37) v1(11.87,37.15) v1(11.87,34.61) v1(11.87,32.07) v1(11.87,26.99) v1(11.87,24.45) v1(11.87,20.96) v1(11.87,18.42) v1(12.51,14.29) v1(12.51,11.75) v1(12.51,9.21) v1(12.83,4.13) v1(14.41,47.37) v1(14.41,40.64) v1(14.41,37.15) v1(14.41,34.61) v1(14.41,32.07) v1(14.41,26.99) v1(14.41,24.45) v1(14.41,20.96) v1(15.05,11.75) v1(15.05,9.21) v1(15.68,4.13) v1(16.95,47.37) v1(16.95,40.64) v1(16.95,37.15) v1(16.95,34.61) v1(16.95,32.07) v1(16.95,24.45) v1(16.95,20.96) v1(17.59,14.29) v1(17.59,11.75) v1(17.59,9.21) v1(17.59,6.67) v1(18.22,4.13) v1(19.49,47.37) v1(19.49,45.72) v1(19.49,43.18) v1(19.49,40.64) v1(19.49,37.15) v1(19.49,34.61) v1(19.49,32.07) v1(20.13,16.83) v1(20.13,14.29) v1(20.13,11.75) v1(20.13,9.21) v1(20.13,6.67) v1(20.76,4.13) v1(20.76,1.84) v1(22.03,32.07) v1(22.03,7.49) v1(22.03,6.54) v1(22.67,16.83) v1(22.67,14.29) v1(22.67,5.59) v1(23.62,4.13) v1(23.62,1.84) v1(23.94,5.59) v1(24.57,32.07) v1(24.57,30.16) v1(24.57,27.94) v1(25.21,16.83) v1(25.53,24.77) v1(25.53,14.29) v1(25.84,21.27) v1(26.16,4.13) v1(26.16,1.84) v1(27.11,32.07) v1(27.11,30.16) v1(27.11,27.94) v1(27.43,16.83) v1(28.07,24.77) v1(28.07,14.29) v1(28.07,12.38) v1(28.38,21.27) v1(29.02,4.13) v1(29.02,1.84) v1(29.65,32.07) v1(29.65,30.16) v1(29.65,27.94) v1(30.61,24.77) v1(30.92,21.27) v1(31.24,12.38) v1(32.19,32.07) v1(32.19,30.16) v1(33.46,21.27) v1(33.78,17.46) v1(33.78,14.92) v1(33.78,12.38) v1(34.73,32.07) v1(36.32,23.81) v1(36.32,21.27) v1(36.32,17.46) v1(36.32,14.92) v1(36.32,12.38) v1(36.96,4.76) v1(36.96,2.22) v1(37.78,31.75) v1(37.78,30.8) v1(38.29,27.56) v1(38.29,22.61) v1(38.29,21.21) v1(38.86,17.46) v1(39.5,4.76) v1(39.5,2.22) v1(39.81,42.55) v1(39.81,40.64) v1(39.81,38.42) v1(40.83,28.07) v1(41.72,17.46) v1(41.72,14.92) v1(41.72,12.38) v1(42.35,42.55) v1(42.35,40.64) v1(42.35,38.42) v1(42.35,35.56) v1(42.35,4.76) v1(42.35,2.22) v1(42.67,31.43) v1(42.67,29.53) v1(42.67,27.3) v1(42.67,25.4) v1(43.5,13.21) v1(43.5,11.94) v1(43.94,21.27) v1(44.89,42.55) v1(44.89,40.64) v1(44.89,38.42) v1(45.21,33.66) v1(45.21,31.43) v1(45.21,25.4) v1(46.48,28.38) v1(46.48,27.11) v1(47.12,37.78) v1(50.61,26.04) v1(50.93,21.91) v1(52.2,38.1) v1(52.2,4.76) v1(52.2,2.22) v1(53.15,26.04) v1(53.15,23.5) v1(54.42,15.88) v1(54.42,13.97) v1(54.42,12.06) v1(54.74,38.1) v1(56.01,23.5) v1(57.28,38.1) v1(57.28,35.88) v1(57.91,13.46) v1(58.86,26.16) v1(59.82,13.46) v1(60.45,40.01) v1(61.09,16.83) v1(61.4,29.21) v1(63.31,27.3) v1(63.31,16.83) v1(64.83,30.1) v1(65.85,11.81) v1(67.63,13.59) v1(67.75,11.68) v1(70.29,30.16) v1(71.06,40.89) v1(71.56,30.16) v1(73.22,40.89) v1(73.15,21.59) v1(73.15,19.69) v1(74.74,39.62) v1(74.74,38.1) v1(75.25,40.89) v1(75.37,21.59) v1(75.37,19.69) v1(77.6,36.83) v1(77.6,34.61) v1(77.66,38.73) v1(77.79,40.89) v1(78.23,23.81) v1(78.23,21.59) v1(80.2,26.04) v1(80.71,21.72)
DGND: length 95.3
  TOP w0.254: v1(92.27,25.78) 92.08,25.97 U7.11 90.01,25.97 89.22,26.76 v1(89.22,27.05)
  TOP w0.508: U6.6 81.28,11.11 v1(80.64,11.75) ; v1(80.64,11.75) v1(80.64,13.02) v1(80.64,14.22) ; v1(80.64,11.75) 80.01,11.11 U6.3 ; v1(80.64,11.75) v1(80.64,10.48) v1(80.64,9.27)
  TOP w0.635: C28.N 66.7,37.27 ; C28.N 65.72,38.67 ; C28.N 64.74,37.27 ; 67.28,36.09 C29.2 68.26,37.02 ; v1(57.37,1.94) POWER.C v1(58.42,3.15) ; C12.G1 v1(88.96,14.54) ; DGND1.1 34.8,42.55 ; DGND1.1 33.66,43.69 ; DGND1.1 32.51,42.55 ; DGND1.1 33.66,41.4 ; 99.38,24.19 99.38,25.4 100.58,25.4 ; v1(85.38,22.57) R18.2 v1(84.01,23.94) ; C21.1 90.01,35.52 ; C21.1 88.05,35.52 ; C21.1 89.03,36.45 ; C12.G2 v1(88.96,11.37) ; R31.2 68.68,39.4 ; R31.2 67.75,38.42 ; R31.2 68.68,37.44 ; v1(84.59,15.42) C13.2 v1(86.17,16.64) ; 75.31,2.54 P1.7 76.52,3.75 ; DGND2.1 96.84,19.24 ; DGND2.1 96.84,16.95 ; DGND2.1 95.69,18.1 ; DGND2.1 97.98,18.1 ; 75.18,2.54 73.98,2.54 73.98,3.75 ; v1(75.18,9.59) C14.2 v1(73.98,10.64) ; v1(83.67,35.05) C22.2 v1(82.55,33.78)
  L2_GND w0.635: DGND1.1 34.8,42.55 ; DGND1.1 33.66,41.4 ; DGND1.1 32.51,42.55 ; DGND1.1 33.66,43.69 ; 75.18,2.54 73.98,2.54 73.98,3.75 ; 95.69,18.1 DGND2.1 ; DGND2.1 96.84,19.24 ; DGND2.1 97.98,18.1 ; DGND2.1 96.84,16.95 ; 76.52,3.75 P1.7 75.31,2.54 ; 100.58,25.4 99.38,25.4 99.38,24.19
  BOTTOM w0.635: DGND1.1 34.8,42.55 ; DGND1.1 33.66,41.4 ; DGND1.1 33.66,43.69 ; DGND1.1 32.51,42.55 ; Q4.2 26.4,46.2 ; Q4.2 25.51,47.28 ; Q4.2 25.51,45.12 ; 100.58,25.4 99.38,25.4 99.38,24.19 ; 29.64,45.12 Q3.2 ; Q3.2 29.64,47.28 ; Q3.2 30.53,46.2 ; 76.52,3.75 P1.7 75.31,2.54 ; 73.98,3.75 73.98,2.54 75.18,2.54 ; DGND2.1 97.98,18.1 ; DGND2.1 95.69,18.1 ; DGND2.1 96.84,19.24 ; DGND2.1 96.84,16.95
  vias: v1(23.62,50.8) v1(26.16,50.8) v1(28.7,50.8) v1(31.24,44.45) v1(31.24,42.55) v1(31.24,40.32) v1(31.24,38.42) v1(31.56,50.8) v1(32.19,36.51) v1(32.19,34.61) v1(33.78,40.32) v1(33.78,38.42) v1(34.1,50.8) v1(34.73,36.51) v1(34.73,34.61) v1(36.19,42.55) v1(36.19,40.32) v1(36.19,38.42) v1(36.64,50.8) v1(39.5,50.8) v1(39.5,48.26) v1(42.04,50.8) v1(42.04,48.26) v1(44.58,50.8) v1(44.58,48.26) v1(49.02,46.99) v1(51.56,47.94) v1(51.56,45.72) v1(60.9,6.86) v1(60.9,4.83) v1(63.56,6.86) v1(63.56,4.83) v1(64.9,40.64) v1(64.9,39.69) v1(66.04,40.64) v1(66.04,39.69) v1(66.23,6.86) v1(66.23,4.83) v1(68.64,6.86) v1(68.64,4.83) v1(70.8,7.87) v1(73.47,7.87) v1(74.42,4.45) v1(75.69,7.94) v1(76.96,4.45) v1(78.23,7.94) v1(78.87,4.45) v1(81.09,7.94) v1(81.41,4.45) v1(81.98,16) v1(82.99,21.27) v1(82.99,18.73) v1(83.63,40.32) v1(83.63,37.78) v1(83.63,7.94) v1(85.53,21.27) v1(85.53,18.73) v1(86.17,40.32) v1(86.17,37.78) v1(86.17,12.06) v1(86.17,10.54) v1(87.69,30.8) v1(87.69,28.26) v1(87.69,11.05) v1(88.07,21.27) v1(88.07,18.73) v1(88.07,16.19) v1(88.46,38.73) v1(88.46,36.96) v1(89.03,5.08) v1(89.6,36.96) v1(90.61,21.27) v1(90.61,18.73) v1(90.61,16.19) v1(90.74,23.88) v1(91.88,5.08) v1(93.15,23.81) v1(93.15,21.27) v1(93.15,18.73) v1(93.15,16.19) v1(93.15,13.65) v1(93.15,10.99) v1(93.15,9.84) v1(94.3,43.81) v1(94.42,10.99) v1(94.42,9.84) v1(94.74,5.08) v1(95.31,42.04) v1(95.69,23.81) v1(95.69,21.27) v1(95.69,10.99) v1(95.69,9.84) v1(96.01,16.19) v1(96.01,13.65) v1(96.33,43.81) v1(96.58,33.66) v1(96.96,40.32) v1(96.96,37.78) v1(97.28,5.08) v1(98.23,23.81) v1(98.23,21.27) v1(98.87,16.19) v1(98.87,13.65) v1(98.87,11.11) v1(99.19,41.59) v1(99.19,39.05) v1(99.5,51.75) v1(99.5,49.21) v1(99.82,46.67) v1(99.82,44.13) v1(99.82,18.73) v1(100.77,23.81) v1(100.77,21.27) v1(101.28,16.19) v1(101.28,13.65) v1(101.28,11.11)
CS: length 14.4
  TOP w0.254: v1(76.14,29.21) 77.91,29.21 78.31,29.6 RN1.14 ; U1.2 v1(68.42,27.3)
  BOTTOM w0.254: v1(68.42,27.3) 68.42,28.47 68.69,28.75 75.68,28.75 v1(76.14,29.21)
CS1: length 39.5
  TOP w0.254: U7.16 92.76,29.22 92.77,29.2 v1(92.83,29.2)
  BOTTOM w0.254: v1(92.83,29.2) 93.47,29.85 93.47,29.88 93.48,29.89 93.48,39.04 88.07,44.45 79.78,44.45 78.77,43.43 72.2,43.43 70.93,44.7 AD7798_CS.2
CS2: length 27.9
  TOP w0.254: U7.15 90.82,28.56 v1(93.47,28.56)
  BOTTOM w0.254: v1(93.47,28.56) 94.21,29.29 94.21,39.59 88.71,45.09 84.39,45.09 AD5270_CS.2
CS3: length 23.4
  TOP w0.254: v1(94.42,27.94) 94.39,27.91 93.2,27.91 93.2,27.92 U7.14
  BOTTOM w0.254: ADT7310_CS.2 92.61,45.5 92.61,42.77 94.74,40.64 94.74,28.26 v1(94.42,27.94)
CS_POT: length 70
  TOP w0.254: v1(77.53,28.45) 77.85,28.45 78.51,29.1 RN1.15 ; v1(50.29,24.13) 50.29,24.59 49.39,25.49 U2.10 ; U3.10 49.39,9.6 v1(49.85,9.14)
  BOTTOM w0.254: v1(50.29,24.13) 49.47,23.3 49.47,9.53 v1(49.85,9.14) 57.72,9.14 66.23,17.65 66.23,28.7 69.66,32.13 76.8,32.13 77.17,31.76 77.17,30.63 76.9,30.35 76.9,29.08 v1(77.53,28.45)
CS_TEMP: length 67.4
  TOP w0.254: v1(78.55,27.94) 78.55,28.28 78.87,28.6 RN1.16 ; U4.4 v1(34.86,10.92)
  BOTTOM w0.254: v1(34.86,10.92) 33.72,9.78 33.72,6.73 34.23,6.22 35.37,6.22 36.64,7.49 48.32,7.49 48.7,7.11 58.23,7.11 68.64,17.53 68.64,25.65 69.96,26.97 77.58,26.97 78.55,27.94 v1(78.55,27.94)
CT_TEMP: length 12.4
  TOP w0.254: R34.2 30.3,3.9 30.3,8.88 29.53,9.65 U4.6 26.42,9.65 26.16,9.4 R21.2
DC: length 20.2
  TOP w0.254: v1(46.48,12.38) 46.52,12.38 46.96,11.94 47.88,11.94 48.39,11.44 U3.8 ; v1(45.95,24.13) 45.95,24.09 R19.1 47.05,24.77 47.89,25.6 U2.7
  BOTTOM w0.254: v1(45.95,24.13) 44.89,23.08 44.89,13.97 v1(46.48,12.38)
INT: length 23.7
  TOP w0.254: U7.13 92.24,27.27 92.52,26.99 v1(93.15,26.99)
  BOTTOM w0.254: v1(93.15,26.99) 94.42,26.99 95.38,27.94 95.38,40.32 97.92,42.86 R32.1
INT_TEMP: length 11.6
  TOP w0.254: R20.2 26.44,10.92 U4.5 29.21,10.92 30.92,9.21 30.92,5.5 R33.2
IOREF: length 9.3
  TOP w0.254: 89.34,31.43 89.61,31.17 U7.19
  TOP w0.762: 89.34,31.43 89.03,31.75 C21.2 v1(90.61,33.82)
  L3_PWR w0.508: 65.02,2.54 P1.2 62.61,2.54
  L3_PWR w0.635: P1.2 63.82,3.75
LED1: length 53.2
  TOP w0.508: v1(74.99,44.2) 74.1,43.31 64.83,43.31 61.23,39.7 61.23,39.68 60.65,39.11 v1(59.37,39.11)
  BOTTOM w0.508: v1(59.37,39.11) 53.79,39.11 48.46,44.44 37.66,44.44 33.34,48.77 R27.1 ; R35.1 75.67,45.38 74.99,44.7 v1(74.99,44.2)
LED2: length 60.3
  TOP w0.508: v1(59.37,40.01) 59.68,40.31 59.68,40.33 60.13,40.78 61.04,40.78 65.23,44.97 76.63,44.97 v1(77.28,44.32)
  BOTTOM w0.508: R36.1 77.28,44.87 v1(77.28,44.32) ; v1(59.37,40.01) 54.17,40.01 48.83,45.34 38.04,45.34 33.35,50.03 28.38,50.03 28.37,50.04 26.48,50.04 25.3,48.86 R29.1
MISO: length 69.9
  TOP w0.254: R22.1 v1(47.4,9.39) 47.89,9.88 U3.7 ; v1(76.41,31.38) 76.42,31.37 78.79,31.37 79.06,31.1 RN1.11 ; U4.2 v1(37.4,8.38) ; v1(69.02,29.46) 68.42,30.07 U1.15
  BOTTOM w0.254: v1(76.41,31.38) 76.41,30.62 75.25,29.46 v1(69.02,29.46) 68.64,29.46 67.77,28.59 67.77,17.54 57.98,7.75 49.03,7.75 v1(47.4,9.39) 46.39,8.38 v1(37.4,8.38)
MISO_ARD: length 45.2
  TOP w0.254: U7.20 v1(92.13,31.82) 95.5,31.82 ICSP.1
  BOTTOM w0.254: v1(92.13,31.82) 92.13,37.85 86.8,43.18 79.81,43.18 79.1,42.47 70.37,42.47 68.71,44.13 64.68,44.13 R15.1
MOSI: length 86.1
  TOP w0.254: U4.3 v1(35.12,9.65) ; v1(66.99,30.48) 67.25,30.48 67.77,31 U1.16 ; U2.8 v1(48.39,24.77) ; v1(48.07,13.08) v1(50.23,13.08) ; RN1.13 v1(77.66,30.1)
  BOTTOM w0.254: v1(77.66,30.1) 77.66,32.13 77.2,32.59 69.1,32.59 v1(66.99,30.48) 65.6,29.08 65.6,17.91 57.47,9.78 50.61,9.78 50.23,10.16 v1(50.23,13.08) ; v1(48.39,24.77) 48.07,24.45 v1(48.07,13.08) 48.07,11.68 47.05,10.67 36.13,10.67 v1(35.12,9.65)
MOSI_ARD: length 50.7
  TOP w0.254: 99.38,27.94 98.22,26.78 95.58,26.78 95.19,27.18 95.19,28.58 93.6,30.16 v1(92.84,30.16) 92.54,29.87 U7.17
  BOTTOM w0.254: R14.1 66.33,44.7 69.09,44.7 70.87,42.93 78.91,42.93 79.92,43.94 87.31,43.94 92.84,38.42 v1(92.84,30.16)
SCLK: length 87.1
  TOP w0.254: v1(49.12,24.07) 49.12,25.11 48.89,25.34 U2.9 ; U1.1 67.77,27.45 v1(66.99,28.22) ; v1(75.63,30.95) 75.86,30.72 77.42,30.72 77.56,30.86 78.56,30.86 78.81,30.6 RN1.12 ; U3.9 v1(48.89,9.02) ; U4.1 v1(34.68,7.11)
  BOTTOM w0.254: v1(49.12,24.07) 48.89,23.84 48.89,9.09 ; 48.89,9.09 47.94,10.03 37.6,10.03 v1(34.68,7.11) ; 48.89,9.09 v1(48.89,9.02) 48.89,8.96 49.47,8.38 57.87,8.38 66.99,17.5 v1(66.99,28.22) 66.99,28.7 69.24,30.95 v1(75.63,30.95)
SCLK_ARD: length 51.2
  TOP w0.254: ICSP.3 96.84,28.07 93.85,31.05 92.16,31.05 91.62,30.52 U7.18 v1(89.42,30.52)
  BOTTOM w0.254: R16.1 63.09,43.5 68.39,43.5 69.98,41.91 79.18,41.91 79.82,42.55 86.49,42.55 91.57,37.47 91.57,32.67 v1(89.42,30.52)
UNNAMED_6_AD5X7X_I72_A: length 18.4
  TOP w0.254: U3.2 48.89,16.5 R12.2 52.1,17.27 C23.2 53.81,17.37 v1(53.91,17.27) ; A1.7 v1(58.87,22.67) 58.87,21.31 R13.1
  BOTTOM w0.254: v1(53.91,17.27) 54.42,17.78 54.42,20.64 55.05,21.27 57.48,21.27 v1(58.87,22.67)
UNNAMED_6_AD5X7X_I72_EXTCAP: length 3.2
  TOP w0.254: C16.1 46.82,13.68 47.39,14.24 U3.5
UNNAMED_6_AD5X7X_I72_W: length 2.9
  TOP w0.254: R25.2 47.97,16.52 47.97,16.41 48.39,16 U3.3
UNNAMED_6_AD5X7X_I117_A: length 18.7
  TOP w0.254: A1.1 v1(59.52,29.71) 59.52,31 R9.1 ; v1(54.1,33.46) 54,33.57 C8.2 52.1,33.46 R8.2 48.89,32.69 U2.2
  BOTTOM w0.254: v1(54.1,33.46) 54.1,31.12 56.32,28.89 58.71,28.89 v1(59.52,29.71)
UNNAMED_6_AD5X7X_I117_EXTCAP: length 3.3
  TOP w0.254: U2.5 47.39,30.24 47.02,29.87 C11.1
UNNAMED_6_AD5X7X_I117_W: length 2.9
  TOP w0.254: R24.2 47.75,32.93 47.75,32.83 48.39,32.19 U2.3
UNNAMED_6_AD779X_I99_AIN3NEGP2: length 68.9
  TOP w0.254: U1.4 69.72,27.36 70.62,28.27 72.82,28.27 73.25,27.84 C26.1 75.16,27.84 75.69,27.3 75.69,24.45 75.06,23.81 71.88,23.81 60.45,12.38 56.96,12.38 56.01,13.33 56.01,18.04 53.73,20.32 45.21,20.32 43.94,19.05 32.53,19.05 RT1.1 31.56,18.08 R26.1
UNNAMED_6_ADA45282_I56_: length 3.5
  TOP w0.254: R11.2 56.86,25.63 57.57,24.91 A1.5
UNNAMED_6_ADA45282_I56__1: length 15.7
  TOP w0.254: v1(53.47,19.37) 52.49,19.37 C23.1 52.1,19.18 R12.1 47.22,19.18 R25.1 ; R10.2 v1(56.64,22.35) 57.7,22.35 58.22,22.88 A1.6
  BOTTOM w0.254: v1(53.47,19.37) 53.47,20.96 54.86,22.35 v1(56.64,22.35)
UNNAMED_6_ADA45282_I112_: length 18
  TOP w0.254: A1.2 58.87,29.2 58.42,29.65 v1(56.96,29.65) R5.2 ; v1(53.78,35.37) 53.68,35.27 C8.1 52.1,35.37 R8.1 47.22,35.37 R24.1
  BOTTOM w0.254: v1(56.96,29.65) 55.05,31.56 55.05,34.1 v1(53.78,35.37)
UNNAMED_6_ADA45282_I112__1: length 4.5
  TOP w0.254: A1.3 58.22,27.58 58.48,27.33 R7.2
UNNAMED_6_ADOPAMP1V4_I123_INV: length 6.9
  TOP w0.254: A2.2 40.01,28.9 39.41,28.3 38.47,28.3 38.29,28.47 C3.1 36.41,28.58 R2.1
UNNAMED_6_ADOPAMP1V4_I123_NINV: length 2.2
  TOP w0.254: A2.3 39.36,32.16 R1.2
UNNAMED_6_ADOPAMP1V4_I123_OUT: length 20.4
  TOP w0.254: M1.2 32.06,23.04 34.29,25.27 C4.1 C3.2 38.63,26.77 39.36,26.04 A2.6
UNNAMED_6_CAP_I58_N2: length 4.4
  TOP w0.254: R2.2 34.71,29.82 34.29,29.4 C4.2 R3.1
UNNAMED_6_CAP_I76_N1: length 19.6
  TOP w0.254: 58.86,19.49 59.94,18.42 64.9,18.42 71.3,24.82 71.32,24.82 71.51,25.01 71.51,25.03 71.67,25.18 U1.7 ; 58.86,19.49 C24.1 ; 58.86,19.49 R13.2
UNNAMED_6_CAP_I106_N1: length 20.8
  TOP w0.254: C9.1 R9.2 59.6,32.73 65.2,27.13 65.2,24.78 66.81,23.16 68.69,23.16 70.37,24.84 U1.5
UNNAMED_6_DIOLED_I150_N: length 2.4
  TOP w0.508: LED1.C 28.83,42.42 v1(28.7,42.55)
  BOTTOM w0.508: Q3.3 v1(28.7,42.55)
UNNAMED_6_DIOLED_I150_P: length 2.7
  TOP w0.508: LED1.A v1(28.83,39.18)
  BOTTOM w0.508: R28.2 28.7,39.05 v1(28.83,39.18)
UNNAMED_6_DIOLED_I151_N: length 2.6
  TOP w0.508: LED2.C 24.45,42.35 v1(24.26,42.55)
  BOTTOM w0.508: v1(24.26,42.55) 24.32,42.55 24.57,42.8 Q4.3
UNNAMED_6_DIOLED_I151_P: length 2.3
  TOP w0.508: v1(24.57,38.73) 24.45,38.86 LED2.A
  BOTTOM w0.508: R30.2 v1(24.57,38.73)
UNNAMED_6_MODCOHA2_I100_RE: length 56.9
  TOP w0.254: R3.2 21.82,26.77 18.09,23.04 M1.4 8.9,23.04 8.7,23.24 8.7,43.81 8.31,44.21 Q2.1 8.31,45.64 9.02,46.36 15.37,46.36 15.86,45.86 Q1.1
UNNAMED_6_RES_I73_N2: length 3.7
  TOP w0.254: Q1.3 14.86,42.32 R4.2
UNNAMED_6_RES_I121_N2: length 4.2
  TOP w0.254: Q2.3 4.93,42.19 4.8,42.32 R23.2
UNNAMED_6_RES_I138_N2: length 2.6
  BOTTOM w0.508: Q3.1 27.76,48.74 R27.2
UNNAMED_6_RES_I142_N2: length 2.6
  BOTTOM w0.508: Q4.1 23.63,48.73 R29.2
UNNAMED_7_ADP7102_I29_ENUVLO: length 10
  TOP w0.508: U6.5 84.14,9.84 84.77,10.48 84.77,13.42 85,13.65 ; 85,13.65 U6.8 ; 85,13.65 85.06,13.72 C13.1 87.2,13.72 C12.3
UNNAMED_7_CAP4PV3_I7_IN: length 8.8
  TOP w0.635: CR1.C 89.76,9.66 89.97,9.87 C12.1
  TOP w1.016: CR1.C 88.72,9.12 F1.2
UNNAMED_7_DIOLED_I21_P: length 18.3
  TOP w0.762: POWER.A 57.37,6.12 60.01,8.76 68.52,8.76 70.4,10.64 R6.2
UNNAMED_8_CN3P_I101_N1: length 5.1
  BOTTOM w0.254: AD5270_CS.1 85.66,49.28 DIGI0.6
UNNAMED_8_CN3P_I101_N3: length 4.9
  BOTTOM w0.254: 81.6,50.8 80.58,49.78 AD5270_CS.3
UNNAMED_8_CN3P_I102_N1: length 6.9
  BOTTOM w0.254: ADT7310_CS.1 91.63,49.02 91,49.02 89.22,50.8
UNNAMED_8_CN3P_I102_N3: length 5.5
  BOTTOM w0.254: 89.22,46.36 89.22,48.26 DIGI0.5
UNNAMED_8_CN8PA_I81_N3: length 7.7
  BOTTOM w0.254: DIGI0.3 93.41,49.15 96.08,49.15 97.92,47.31 R32.2
UNNAMED_8_CN8PA_I81_N8: length 4.2
  BOTTOM w0.508: R36.2 77.79,49.53 DIGI0.8
UNNAMED_8_CN10P_I85_N1: length 4
  BOTTOM w0.508: DIGI1.1 75.76,50.04 R35.2
UNNAMED_8_CN10P_I85_N2: length 4.9
  BOTTOM w0.254: AD7798_CS.1 72.45,47.37 DIGI1.2
UNNAMED_8_CN10P_I85_N3: length 5.1
  BOTTOM w0.254: DIGI1.3 69.91,47.88 AD7798_CS.3
UNNAMED_8_CN10P_I85_N4: length 4.4
  BOTTOM w0.254: R14.2 65.53,48.96 DIGI1.4
UNNAMED_8_CN10P_I85_N5: length 4.2
  BOTTOM w0.254: DIGI1.5 63.31,49.28 R15.2
UNNAMED_8_CN10P_I85_N6: length 4.1
  BOTTOM w0.254: R16.2 61.09,49.59 62.29,50.8
UNNAMED_8_CN10P_I85_N7: length 7.6
  BOTTOM w0.254: R17.2 58.55,49.59 DIGI1.7
UNNAMED_8_ICTXB0108_I64_A1: length 3.7
  TOP w0.254: U7.1 83.75,31.82 83.03,31.1 RN1.6
UNNAMED_8_ICTXB0108_I64_A2: length 3.4
  TOP w0.254: RN1.5 83.66,30.6 83.75,30.52 U7.3
UNNAMED_8_ICTXB0108_I64_A3: length 3.5
  TOP w0.254: RN1.4 83.24,30.1 83.48,29.87 U7.4
UNNAMED_8_ICTXB0108_I64_A4: length 3.6
  TOP w0.254: RN1.3 81.56,29.6 81.77,29.6 81.77,29.6 82.06,29.6 82.07,29.59 82.89,29.59 83.26,29.22 U7.5
UNNAMED_8_ICTXB0108_I64_A5: length 3.6
  TOP w0.254: U7.6 83.19,28.57 82.66,29.1 81.57,29.1 RN1.2
UNNAMED_8_ICTXB0108_I64_A6: length 3.7
  TOP w0.254: RN1.1 82.3,28.6 82.99,27.92 U7.7
UNNAMED_8_ICTXB0108_I64_A7: length 63.1
  TOP w0.254: 33.36,2.54 R33.1 35.37,4.76 36.32,5.71 52.26,5.71 57.72,11.18 60.71,11.18 72.07,22.54 79.06,22.54 83.78,27.27 U7.8
WORKER1: length 69.9
  TOP w0.254: R5.1 v1(56.96,33.97) ; M1.1 13.14,28.89 9.97,32.07 9.97,43.5 11.09,44.62 Q1.2
  BOTTOM w0.254: v1(56.96,33.97) 54.1,36.83 46.16,36.83 38.23,28.89 M1.1
WORKER2: length 85.9
  TOP w0.254: R10.1 55.14,19.6 53.8,20.94 44.88,20.94 43.62,19.69 19.07,19.69 M1.3 15.58,16.19 8.06,16.19 1.71,22.54 1.71,43.18 2.96,44.42 Q2.2

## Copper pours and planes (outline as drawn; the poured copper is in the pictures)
1V2_REF on TOP: 53.34,42.55 54.93,42.55 54.93,42.86 55.24,43.18 58.1,43.18 58.1,47.62 57.15,48.58 54.29,48.58 53.34,47.62
1V2_REF on TOP: 56.32,26.8 54.1,26.8 53.78,27.11 53.78,28.7 54.1,29.02 55.69,29.02 56.32,28.38
1V2_REF on TOP: 30.61,19.05 30.61,16.51 30.29,16.19 28.7,16.19 28.38,16.51 28.38,19.05 28.7,19.37 30.29,19.37
1V2_REF on TOP: 63.94,26.48 60.77,26.48 60.45,26.16 60.45,24.57 60.77,24.26 63.94,24.26 64.26,24.57 64.26,26.16
1V2_REF on TOP: 38.42,33.34 40.32,33.34 40.64,33.66 40.64,35.88 40.32,36.2 38.42,36.2 38.1,35.88 38.1,33.66
1V2_REF on TOP: 72.2,33.02 72.2,30.8 72.83,30.8 72.83,31.12 75.69,31.12 76.01,31.43 76.01,33.34 75.69,33.66 72.83,33.66
1V2_REF on L3_PWR: 25.97,15.49 25.97,32.77 36.6,32.77 36.72,32.64 36.94,32.64 37.08,32.79 37.08,32.85 37.15,32.91 37.15,33.13 37.08,33.19 37.08,44.51 55.18,44.51 55.18,47.69 61.02,47.69 61.02,30.86 66.93,30.86 66.93,34.04 77.22,34.04 77.22,24.38 53.91,24.38 53.91,40.89 41.34,40.89 41.34,15.49
3V3A on TOP: 39.69,26.67 40.64,26.67 40.64,24.45 44.45,24.45 44.77,24.13 44.77,22.54 44.45,22.23 39.37,22.23 39.37,24.13 39.69,24.45
3V3A on TOP: 52.51,12.76 50.93,12.76 50.93,13.65 50.61,13.97 49.28,13.97 49.28,16 49.66,16 50.55,15.11 52.64,15.11 52.83,14.92 52.83,13.08
3V3A on TOP: 71.75,35.24 71.75,37.15 75.25,37.15 75.25,33.97 69.85,33.97 69.91,33.91 69.91,31.12 69.53,31.12 69.53,35.18 69.6,35.24
3V3A on TOP: 50.8,42.23 54.93,42.23 54.93,41.15 54.74,40.96 50.93,40.96 50.61,40.64 50.61,38.42 50.29,38.1 48.58,38.1 48.58,42.55 50.48,42.55
3V3A on TOP: 46.48,8.89 46.48,6.35 46.16,6.03 44.26,6.03 43.94,6.35 43.94,8.89 44.26,9.21 46.16,9.21
3V3A on TOP: 2.35,41.27 3.94,41.27 4.25,40.96 4.25,39.05 3.94,38.73 2.35,38.73 2.03,39.05 2.03,40.96
3V3A on TOP: 53.15,28.96 49.21,28.96 49.21,32.19 49.66,32.19 49.66,30.92 53.15,30.92 53.47,30.61 53.47,29.27
3V3A on TOP: 45.53,21.27 48.07,21.27 48.39,21.59 48.39,22.86 48.07,23.18 45.53,23.18 45.21,22.86 45.21,21.59
3V3A on TOP: 77.15,20.83 77.15,17.14 80.33,17.14 81.09,17.91 81.09,19.94 80.2,20.83
3V3A on TOP: 64.26,21.08 60.45,21.08 60.13,21.4 60.13,22.99 59.18,22.99 59.18,24.89 60.13,24.89 60.13,24.26 60.45,23.94 64.26,23.94 64.58,23.62 64.58,21.4
3V3A on TOP: 10.6,41.27 12.19,41.27 12.51,40.96 12.51,39.05 12.19,38.73 10.6,38.73 10.29,39.05 10.29,40.96
3V3A on TOP: 29.34,6.54 29.34,7.81 24.57,7.81 24.57,5.27 24.89,4.95 26.48,4.95 26.8,5.27 26.8,6.22 27.11,6.54
3V3A on TOP: 24.26,8.13 24.26,13.53 21.72,13.53 21.08,12.89 21.08,8.76 21.72,8.13
3V3A on L3_PWR: 1.46,1.65 1.46,52.2 20.38,52.2 20.38,32.91 20.53,32.77 25.46,32.77 25.46,14.99 41.85,14.99 41.85,40.39 53.4,40.39 53.4,23.88 77.72,23.88 77.72,34.54 66.93,34.54 66.93,42.29 81.66,42.29 81.66,17.4 72.96,17.4 72.96,19.62 68.01,19.62 68.01,10.67 54.29,10.67 54.29,1.65
3V3D on TOP: 70.17,16.19 70.17,12.06 70.48,11.75 79.06,11.75 79.06,16.51 78.74,16.83 76.52,16.83 75.56,17.78 71.75,17.78
3V3D on TOP: 69.28,34.93 66.36,34.93 66.36,35.56 63.5,35.56 63.18,35.24 63.18,32.7 63.5,32.38 66.74,32.38 67.63,33.27 68.77,33.27 68.77,31.12 69.28,31.12
3V3D on TOP: 83.95,31.37 83.95,30.99 86.11,30.99 86.74,31.62 86.74,35.75 86.49,36 84.45,36 84.26,35.81 84.26,33.08 84.65,32.7 85.92,32.7 86.11,32.51 86.11,31.69 85.79,31.37
3V3D on TOP: 86.49,25.08 86.49,22.86 86.8,22.54 89.53,22.54 89.85,22.86 89.85,25.72 89.22,26.35 84.14,26.35 84.14,25.4 84.45,25.08
3V3D on TOP: 23.62,36.83 25.53,36.83 25.84,36.51 25.84,33.97 25.53,33.66 23.62,33.66 23.3,33.97 23.3,36.51
3V3D on BOTTOM: 23.69,34.54 23.69,36.58 25.84,36.58 25.84,34.54
3V3D on BOTTOM: 27.81,34.16 27.81,36.19 29.97,36.19 29.97,34.16
3V3D on L3_PWR: 68.52,10.73 68.52,19.11 72.45,19.11 72.45,16.89 82.17,16.89 82.17,42.8 66.42,42.8 66.42,31.37 61.53,31.37 61.53,48.2 54.82,48.2 54.67,48.05 54.67,45.02 36.72,45.02 36.58,44.87 36.58,33.27 20.89,33.27 20.89,52.2 101.79,52.2 101.79,42.8 87.06,42.8 87.06,28.96 90.23,28.96 90.23,10.73
AGND on TOP: 2.94,1.42 2.68,2.75 1.33,2.9 1.33,50.29 1.46,50.42 2.76,50.73 2.81,52.07 20.76,52.07 20.76,32.38 36.89,32.38 36.89,44.13 60.45,44.13 61.4,43.18 61.4,39.05 62.36,38.1 69.66,38.1 69.98,38.42 69.98,42.16 81.6,42.16 81.6,21.08 76.64,21.08 76.64,18.29 71.56,18.29 69.66,16.38 69.66,11.56 68.77,10.67 53.91,10.67 53.91,1.4 2.96,1.4 ; 11 cut-outs
AGND on BOTTOM: 2.98,1.52 2.69,2.74 1.46,2.96 1.46,50.38 2.84,50.77 2.76,52.2 20.64,52.2 20.64,32.77 37.08,32.77 37.08,44.51 55.18,44.51 55.18,47.69 61.02,47.69 61.02,30.86 66.93,30.86 66.93,42.29 81.66,42.29 81.66,17.4 72.96,17.4 72.96,19.62 68.01,19.62 68.01,10.73 54.36,10.73 54.36,1.52 ; 10 cut-outs
AGND on L2_GND: 1.33,1.4 1.33,52.32 20.64,52.32 20.64,32.77 37.15,32.77 37.15,44.58 55.18,44.58 55.18,47.62 61.02,47.62 61.02,30.86 66.87,30.86 66.87,42.29 81.72,42.29 81.72,17.4 72.96,17.4 72.96,19.69 68.01,19.69 68.01,10.67 54.29,10.67 54.29,1.4
DGND on TOP: 54.67,1.4 54.67,10.16 67.76,10.16 67.76,9.22 68.33,9.22 69.27,10.16 79.31,10.16 79.31,16.64 79.44,16.76 81.98,16.76 81.98,42.67 69.34,42.67 69.34,39.05 69.22,38.93 69.22,35.24 66.99,35.24 66.99,35.88 64.45,35.88 64.13,36.2 64.13,38.73 62.36,38.73 62.04,39.05 62.04,44.13 58.86,44.13 58.55,44.45 58.55,47.94 57.59,48.9 54.1,48.9 53.15,47.94 53.15,45.09 52.83,44.77 36.51,44.77 36.51,33.02 21.4,33.02 21.4,52.07 101.79,52.07 101.79,8.64 101.81,8.62 101.81,2.95 100.45,2.73 100.24,1.38 100.22,1.4 ; 7 cut-outs
DGND on BOTTOM: 54.86,1.4 54.86,10.22 68.52,10.22 68.52,19.11 72.45,19.11 72.45,16.89 82.17,16.89 82.17,42.8 66.42,42.8 66.42,31.37 61.53,31.37 61.53,48.2 54.67,48.2 54.67,45.02 36.58,45.02 36.58,33.27 21.15,33.27 21.15,52.2 101.66,52.2 101.66,2.93 100.46,2.63 100.32,1.4 ; 6 cut-outs
DGND on L2_GND: 54.8,1.4 54.8,10.16 68.52,10.16 68.52,19.18 72.45,19.18 72.45,16.89 82.23,16.89 82.23,42.8 66.36,42.8 66.36,31.37 61.53,31.37 61.53,48.13 54.67,48.13 54.67,45.09 36.64,45.09 36.64,33.27 21.15,33.27 21.15,52.32 101.79,52.32 101.79,1.4
IOREF on L3_PWR: 54.8,1.4 54.8,10.16 90.74,10.16 90.74,29.46 87.57,29.46 87.57,42.29 101.79,42.29 101.79,1.4

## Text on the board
User.Comments: Assembly Notes: | DIGI1, DIGI0, POWER, ANALOG, ICSP | 1. Don't cut the excess pins of the following connectors: | 2. ADD SHUNT ( M00389) FOR AD7798_CS, AD5270_CS AND ADT7310_CS ( PINS 2 AND 3)
Ref Des/Silkscreen Top: EVAL-CN0396-ARDZ REV.B | D10 | D9 | D6 | D5 | D4 | D3 | SCL | SDA | AREF | GND | 13 | IOREF | 12 | RESET | 11 | 3.3V | 10 | 5V | 9 | 8 | 7 | Vin | 6 | A0 | 5 | 4 | A1 | 3 | A2 | A3 | 2 | 1 | A4 | TX1 | 0 | A5 | RX1
PAGE_OUTLINE: N/A | APR14 | MAR16 | B | AS PER ECR 064109 | 16AUG16 | J.CHUA | CN0396-ARDZ EVAL BOARD
DIMENSION: (REF)
DISPLAY_BOTTOM: 100 MICRO INCHES NICKEL/ | 3-5 MICRO INCHES GOLD
User.8: 08-      -01 | LAYER1 PRIMARY SIDE
User.9: 08-      -02 | LAYER2 SECONDARY SIDE
User.11: 08-      -07 | LAYER2_AGND
User.12: 08-      -08 | LAYER3_DGND
User.14: SECONDARY SIDE PASTEMASK | 08-      -12
User.17: L2 GND | 08-      -07
User.18: L3 PWR | 08-      -08
User.27: B
User.28: B
User.32: FIGURE | SIZE | 12.0 | 40.0 | 45.0 | 110.0 | 125.0 | PLATED | NON-PLATED | FINISHED HOLES IN MILS | ALL UNITS ARE IN MILS | QTY | 482 | 7 | 47 | 4 | TOLERANCE/NOTES
